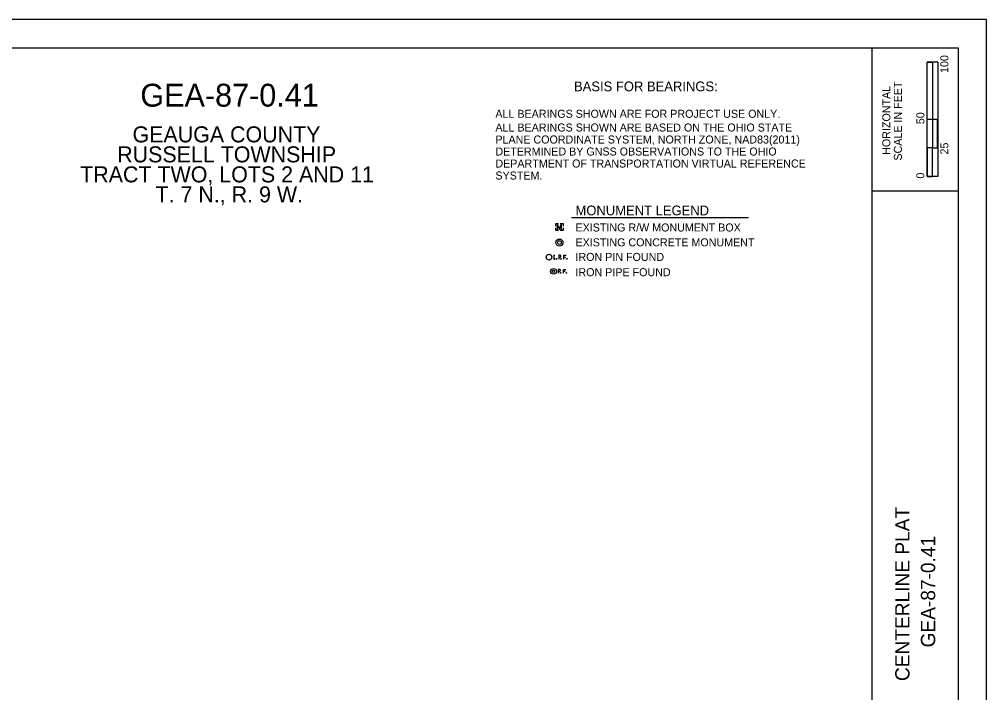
# Model space of a CAD drawing. Extents: x -7 to 3400, y -220 to 22.
# Drawn here: x 17.08 to 34, y 10.22 to 22 of the extents above; entities that cross this region are included whole.
import ezdxf

# ---------------------------------------------------------------- set-up
doc = ezdxf.new("R2010")
doc.units = 0
for name, color, linetype in [('SH_Border', 7, 'Continuous'), ('SH_Cut_Line', 7, 'Continuous'), ('SH_Data', 7, 'Continuous'), ('SH_Text', 7, 'Continuous')]:
    doc.layers.add(name, color=color, linetype=linetype)

msp = doc.modelspace()

# ---------------------------------------------------------------- linework, layer by layer
at = {"layer": 'SH_Border'}
for p, q in [((32, 0.5), (32, 21.5)), ((32, 19), (33.5, 19))]:
    msp.add_line(p, q, dxfattribs=at)
msp.add_lwpolyline([(1.5, 21.5), (33.5, 21.5), (33.5, 0.5), (1.5, 0.5)], close=True, dxfattribs=at)
at = {"layer": 'SH_Cut_Line'}
msp.add_lwpolyline([(0, 0), (34, 0), (34, 22), (0, 22)], close=True, dxfattribs=at)
at = {"layer": 'SH_Data'}
for p, q in [((32.957, 19.25), (32.957, 21.25)), ((33.144, 21.25), (32.957, 21.25)), ((32.957, 20.25), (32.957, 21.25)), ((32.957, 21.25), (33.05, 21.25)), ((33.05, 21.25), (33.051, 21.25)), ((33.051, 21.25), (33.051, 20.25)), ((33.144, 21.25), (33.144, 19.25)), ((33.051, 20.25), (32.957, 20.25)), ((33.143, 20.25), (33.05, 20.25)), ((33.05, 20.25), (33.05, 19.75)), ((33.143, 19.75), (33.143, 20.25)), ((33.05, 19.75), (32.957, 19.75)), ((32.957, 19.75), (32.957, 19.25)), ((33.05, 19.25), (33.05, 19.75)), ((33.05, 19.75), (33.143, 19.75)), ((33.144, 19.25), (32.957, 19.25)), ((32.957, 19.25), (33.05, 19.25))]:
    msp.add_line(p, q, dxfattribs=at)
at = {"layer": 'SH_Text'}
for p, q in [((26.739, 18.534), (29.832, 18.534)), ((26.527, 18.368), (26.527, 18.368)), ((26.429, 17.873), (26.445, 17.873)), ((26.429, 17.873), (26.445, 17.873)), ((26.429, 17.806), (26.445, 17.806)), ((26.437, 17.806), (26.437, 17.873)), ((26.514, 17.841), (26.54, 17.841)), ((26.607, 17.806), (26.607, 17.873)), ((26.607, 17.873), (26.646, 17.873)), ((26.607, 17.841), (26.635, 17.841)), ((26.6, 17.559), (26.6, 17.625)), ((26.6, 17.625), (26.638, 17.625)), ((26.506, 17.593), (26.533, 17.593)), ((26.6, 17.593), (26.627, 17.593))]:
    msp.add_line(p, q, dxfattribs=at)
for points in [[(26.465, 18.383), (26.465, 18.43), (26.512, 18.43)], [(26.512, 18.305), (26.465, 18.305), (26.465, 18.352)], [(26.496, 18.326), (26.496, 18.409), (26.527, 18.326), (26.558, 18.409), (26.558, 18.326)], [(26.542, 18.43), (26.59, 18.43), (26.59, 18.383)], [(26.59, 18.352), (26.59, 18.305), (26.542, 18.305)], [(26.54, 17.873), (26.514, 17.873), (26.514, 17.806)], [(26.533, 17.625), (26.506, 17.625), (26.506, 17.559)]]:
    msp.add_lwpolyline(points, dxfattribs=at)
for centre, radius in [((26.527, 18.095), 0.0625), ((26.527, 18.095), 0.0333), ((26.345, 17.84), 0.05), ((26.477, 17.811), 0.00583), ((26.554, 17.811), 0.00583), ((26.656, 17.811), 0.00583), ((26.423, 17.592), 0.05), ((26.423, 17.592), 0.0206), ((26.547, 17.563), 0.00583), ((26.648, 17.563), 0.00583)]:
    msp.add_circle(centre, radius, dxfattribs=at)
for centre in [(26.538, 17.857), (26.531, 17.609)]:
    msp.add_arc(centre, 0.0162, 278.8803, 81.1197, dxfattribs=at)

# ---------------------------------------------------------------- texts
at = {"layer": 'SH_Data'}
for s, height, p in [('100', 0.14, (33.33, 21.062)), ('HORIZONTAL', 0.14, (32.315, 19.63)), ('SCALE IN FEET', 0.14, (32.517, 19.529)), ('50', 0.14, (32.91, 20.166)), ('25', 0.14, (33.33, 19.636)), ('0', 0.14, (32.91, 19.214)), ('CENTERLINE PLAT', 0.25, (32.65, 10.425)), ('GEA-87-0.41', 0.25, (33.1, 11.013))]:
    msp.add_text(s, height=height, rotation=90, dxfattribs=at).set_placement(p)
at = {"layer": 'SH_Text'}
for s, height, p in [('GEA-87-0.41', 0.4, (19.196, 20.473)), ('BASIS FOR BEARINGS:', 0.17, (26.782, 20.742)), ('ALL BEARINGS SHOWN ARE FOR PROJECT USE ONLY.', 0.14, (25.407, 20.278)), ('ALL BEARINGS SHOWN ARE BASED ON THE OHIO STATE', 0.14, (25.407, 20.038)), ('GEAUGA COUNTY', 0.28, (19.06, 19.848)), ('PLANE COORDINATE SYSTEM, NORTH ZONE, NAD83(2011)', 0.14, (25.407, 19.828)), ('RUSSELL TOWNSHIP', 0.28, (18.792, 19.498)), ('DETERMINED BY GNSS OBSERVATIONS TO THE OHIO', 0.14, (25.407, 19.618)), ('DEPARTMENT OF TRANSPORTATION VIRTUAL REFERENCE', 0.14, (25.407, 19.408)), ('TRACT TWO, LOTS 2 AND 11', 0.28, (18.144, 19.148)), ('SYSTEM.', 0.14, (25.407, 19.198)), ('T. 7 N., R. 9 W.', 0.28, (19.463, 18.798)), ('MONUMENT LEGEND', 0.17, (26.808, 18.572)), ('EXISTING R/W MONUMENT BOX', 0.14, (26.808, 18.289)), ('EXISTING CONCRETE MONUMENT', 0.14, (26.808, 18.029)), ('IRON PIN FOUND', 0.14, (26.808, 17.774)), ('IRON PIPE FOUND', 0.14, (26.808, 17.507))]:
    msp.add_text(s, height=height, dxfattribs=at).set_placement(p)

doc.saveas('drawing.dxf')
